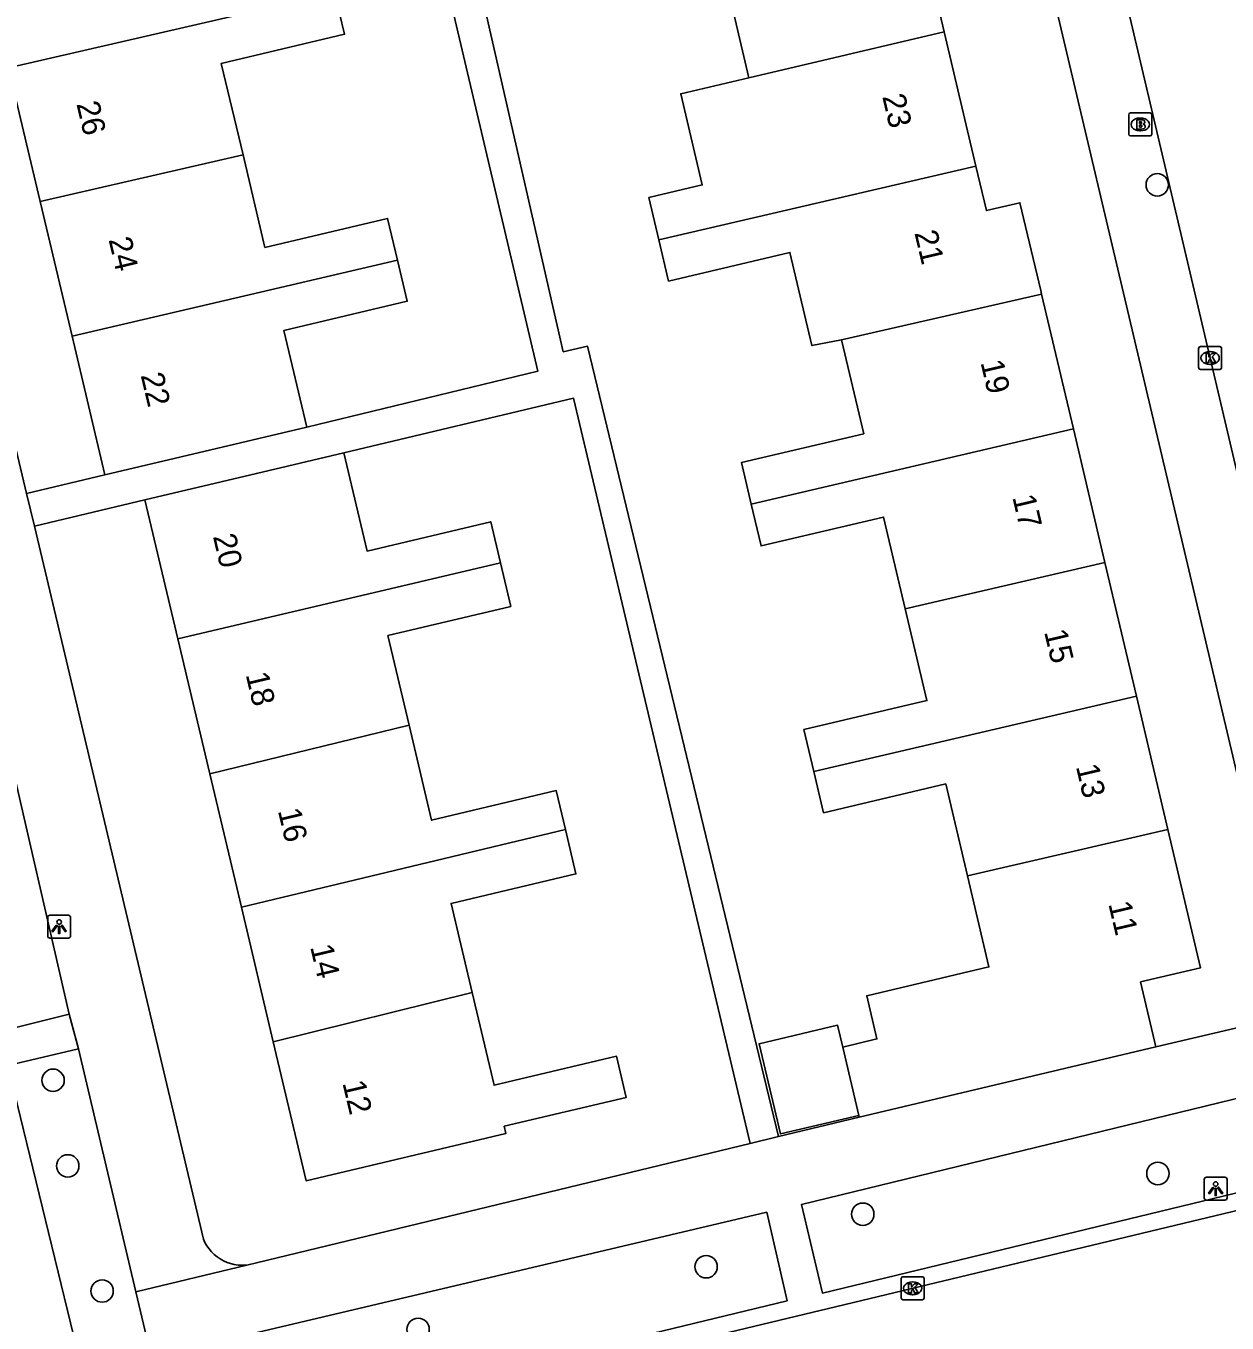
# Model space of a CAD drawing. Extents: x 158038 to 159242, y 380133 to 381214.
# Drawn here: x 158544.2 to 158596.6, y 380781.7 to 380838.3 of the extents above; entities that cross this region are included whole.
import ezdxf

# ---------------------------------------------------------------- set-up
doc = ezdxf.new("R2010")
doc.units = 0
for name, color, linetype in [('IMGEO_Boom', 7, 'Continuous'), ('IMGEO_Brandkraan', 7, 'Continuous'), ('IMGEO_Kolk', 7, 'Continuous'), ('IMGEO_Lichtpunt', 7, 'Continuous'), ('IMGEO_Pand', 7, 'Continuous'), ('IMGEO_Pand_nummerreeks', 7, 'Continuous'), ('IMGEO_Parkeervlak_open', 7, 'Continuous'), ('IMGEO_Rijbaan_lokaal_open', 7, 'Continuous'), ('IMGEO_Voetpad_open', 7, 'Continuous')]:
    doc.layers.add(name, color=color, linetype=linetype)

msp = doc.modelspace()

# ---------------------------------------------------------------- linework, layer by layer
at = {"layer": 'IMGEO_Boom'}
for centre in [(158593.559, 380831.355), (158545.379, 380792.292), (158546.022, 380788.557), (158593.586, 380788.227), (158580.71, 380786.449), (158573.873, 380784.16), (158547.52, 380783.101), (158561.307, 380781.427)]:
    msp.add_circle(centre, 0.489, dxfattribs=at)
at = {"layer": 'IMGEO_Brandkraan'}
for p, q in [((158592.316, 380833.564), (158592.316, 380834.416)), ((158592.391, 380834.49), (158593.243, 380834.49)), ((158592.804, 380834.27), (158592.829, 380834.27)), ((158593.317, 380834.416), (158593.317, 380833.564)), ((158592.827, 380833.71), (158592.802, 380833.71)), ((158593.243, 380833.49), (158592.391, 380833.49))]:
    msp.add_line(p, q, dxfattribs=at)
for points in [[(158592.316, 380833.564), (158592.316, 380834.416)], [(158592.391, 380834.49), (158593.243, 380834.49)], [(158592.664, 380834.19), (158592.664, 380833.79), (158592.877, 380833.79)], [(158592.895, 380834.19), (158592.664, 380834.19)], [(158592.843, 380834.109), (158592.789, 380834.109), (158592.789, 380834.033)], [(158593.317, 380834.416), (158593.317, 380833.564)], [(158592.789, 380834.033), (158592.842, 380834.033)], [(158592.851, 380833.957), (158592.789, 380833.957), (158592.789, 380833.876)], [(158592.789, 380833.876), (158592.851, 380833.876)], [(158593.243, 380833.49), (158592.391, 380833.49)]]:
    msp.add_lwpolyline(points, dxfattribs=at)
for centre, radius, start, end in [((158592.393, 380834.414), 0.0765, 91.552, 178.448), ((158592.393, 380834.414), 0.0765, 91.552, 178.448), ((158592.844, 380834.071), 0.0379, 267.8285, 90.9355), ((158592.899, 380834.045), 0.145, 59.4692, 91.5367), ((158592.924, 380834.092), 0.0922, 285.5137, 58.1501), ((158593.241, 380834.414), 0.0765, 1.552, 88.448), ((158593.241, 380834.414), 0.0765, 1.552, 88.448), ((158592.393, 380833.566), 0.0765, 181.552, 268.448), ((158592.393, 380833.566), 0.0765, 181.552, 268.448), ((158592.852, 380833.916), 0.0404, 269.8759, 90.5077), ((158592.883, 380834.041), 0.251, 268.6676, 293.5347), ((158592.929, 380833.9), 0.105, 301.3115, 78.989), ((158593.241, 380833.566), 0.0765, 271.552, 358.448), ((158593.241, 380833.566), 0.0765, 271.552, 358.448)]:
    msp.add_arc(centre, radius, start, end, dxfattribs=at)
for centre, major_axis, ratio, start_param, end_param in [((158592.803, 380833.99), (-0.387, 0.002), 0.722429, 4.712389, 7.853982), ((158592.828, 380833.99), (-0.39, 0.002), 0.717154, 1.570796, 4.712389)]:
    msp.add_ellipse(centre, major_axis=major_axis, ratio=ratio, start_param=start_param, end_param=end_param, dxfattribs=at)
at = {"layer": 'IMGEO_Kolk'}
for p, q in [((158595.365, 380823.377), (158595.365, 380824.229)), ((158595.44, 380824.303), (158596.292, 380824.303)), ((158595.853, 380824.083), (158595.878, 380824.083)), ((158596.366, 380824.229), (158596.366, 380823.377)), ((158595.876, 380823.523), (158595.851, 380823.523)), ((158596.292, 380823.303), (158595.44, 380823.303)), ((158582.386, 380782.795), (158582.386, 380783.647)), ((158582.461, 380783.721), (158583.313, 380783.721)), ((158582.874, 380783.501), (158582.899, 380783.501)), ((158583.387, 380783.647), (158583.387, 380782.795)), ((158583.313, 380782.721), (158582.461, 380782.721)), ((158582.897, 380782.941), (158582.872, 380782.941))]:
    msp.add_line(p, q, dxfattribs=at)
for points in [[(158595.365, 380823.377), (158595.365, 380824.229)], [(158595.44, 380824.303), (158596.292, 380824.303)], [(158595.686, 380824.003), (158595.809, 380824.003), (158595.809, 380823.852), (158595.939, 380824.003), (158596.103, 380824.003), (158595.957, 380823.852), (158596.11, 380823.603), (158595.958, 380823.603), (158595.873, 380823.767), (158595.809, 380823.7), (158595.809, 380823.603), (158595.686, 380823.603), (158595.686, 380824.003)], [(158596.366, 380824.229), (158596.366, 380823.377)], [(158596.292, 380823.303), (158595.44, 380823.303)], [(158582.386, 380782.795), (158582.386, 380783.647)], [(158582.461, 380783.721), (158583.313, 380783.721)], [(158582.707, 380783.421), (158582.83, 380783.421), (158582.83, 380783.27), (158582.96, 380783.421), (158583.124, 380783.421), (158582.978, 380783.27), (158583.131, 380783.021), (158582.979, 380783.021), (158582.894, 380783.185), (158582.83, 380783.118), (158582.83, 380783.021), (158582.707, 380783.021), (158582.707, 380783.421)], [(158583.387, 380783.647), (158583.387, 380782.795)], [(158583.313, 380782.721), (158582.461, 380782.721)]]:
    msp.add_lwpolyline(points, dxfattribs=at)
for centre, start, end in [((158595.442, 380824.227), 91.552, 178.448), ((158595.442, 380824.227), 91.552, 178.448), ((158596.29, 380824.227), 1.552, 88.448), ((158596.29, 380824.227), 1.552, 88.448), ((158595.442, 380823.379), 181.552, 268.448), ((158595.442, 380823.379), 181.552, 268.448), ((158596.29, 380823.379), 271.552, 358.448), ((158596.29, 380823.379), 271.552, 358.448), ((158582.463, 380783.645), 91.552, 178.448), ((158582.463, 380783.645), 91.552, 178.448), ((158583.311, 380783.645), 1.552, 88.448), ((158583.311, 380783.645), 1.552, 88.448), ((158582.463, 380782.797), 181.552, 268.448), ((158582.463, 380782.797), 181.552, 268.448), ((158583.311, 380782.797), 271.552, 358.448), ((158583.311, 380782.797), 271.552, 358.448)]:
    msp.add_arc(centre, 0.0765, start, end, dxfattribs=at)
for centre, major_axis, ratio, start_param, end_param in [((158595.852, 380823.803), (-0.387, 0.002), 0.722429, 4.712389, 7.853982), ((158595.877, 380823.803), (-0.39, 0.002), 0.717154, 1.570796, 4.712389), ((158582.873, 380783.221), (-0.387, 0.002), 0.722429, 4.712389, 7.853982), ((158582.898, 380783.221), (-0.39, 0.002), 0.717154, 1.570796, 4.712389)]:
    msp.add_ellipse(centre, major_axis=major_axis, ratio=ratio, start_param=start_param, end_param=end_param, dxfattribs=at)
at = {"layer": 'IMGEO_Lichtpunt'}
for p, q in [((158545.147, 380799.399), (158545.147, 380798.592)), ((158545.147, 380799.399), (158545.147, 380798.592)), ((158546.049, 380799.494), (158545.241, 380799.494)), ((158546.049, 380799.494), (158545.241, 380799.494)), ((158546.143, 380798.592), (158546.143, 380799.399)), ((158546.143, 380798.592), (158546.143, 380799.399)), ((158545.241, 380798.498), (158546.049, 380798.498)), ((158545.241, 380798.498), (158546.049, 380798.498)), ((158595.608, 380787.97), (158595.608, 380787.163)), ((158595.608, 380787.97), (158595.608, 380787.163)), ((158596.51, 380788.065), (158595.702, 380788.065)), ((158596.51, 380788.065), (158595.702, 380788.065)), ((158596.604, 380787.163), (158596.604, 380787.97)), ((158596.604, 380787.163), (158596.604, 380787.97)), ((158595.702, 380787.069), (158596.51, 380787.069)), ((158595.702, 380787.069), (158596.51, 380787.069))]:
    msp.add_line(p, q, dxfattribs=at)
for points in [[(158545.521, 380799.063), (158545.56, 380799.035), (158545.372, 380798.773), (158545.334, 380798.8), (158545.521, 380799.063)], [(158545.623, 380799.015), (158545.67, 380799.015), (158545.67, 380798.693), (158545.623, 380798.693), (158545.623, 380799.015)], [(158545.733, 380799.035), (158545.771, 380799.062), (158545.958, 380798.8), (158545.919, 380798.772), (158545.733, 380799.035)], [(158595.982, 380787.634), (158596.021, 380787.606), (158595.833, 380787.344), (158595.795, 380787.371), (158595.982, 380787.634)], [(158596.084, 380787.586), (158596.131, 380787.586), (158596.131, 380787.264), (158596.084, 380787.264), (158596.084, 380787.586)], [(158596.194, 380787.606), (158596.232, 380787.633), (158596.419, 380787.371), (158596.38, 380787.343), (158596.194, 380787.606)]]:
    msp.add_lwpolyline(points, dxfattribs=at)
for centre in [(158545.646, 380799.197), (158596.107, 380787.768)]:
    msp.add_circle(centre, 0.0994, dxfattribs=at)
for centre, start, end in [((158545.241, 380799.399), 90, 180), ((158545.241, 380799.399), 90, 180), ((158546.049, 380799.399), 0, 90), ((158546.049, 380799.399), 0, 90), ((158545.241, 380798.592), 180, 270), ((158545.241, 380798.592), 180, 270), ((158546.049, 380798.592), 270, 0), ((158546.049, 380798.592), 270, 360), ((158595.702, 380787.97), 90, 180), ((158595.702, 380787.97), 90, 180), ((158596.51, 380787.97), 0, 90), ((158596.51, 380787.97), 0, 90), ((158595.702, 380787.163), 180, 270), ((158595.702, 380787.163), 180, 270), ((158596.51, 380787.163), 270, 0), ((158596.51, 380787.163), 270, 360)]:
    msp.add_arc(centre, 0.0946, start, end, dxfattribs=at)
at = {"layer": 'IMGEO_Pand'}
for points in [[(158582.878, 380843.886), (158584.261, 380838.026)], [(158575.745, 380836.029), (158574.791, 380840.071), (158569.436, 380838.807), (158569.011, 380840.606)], [(158543.432, 380836.465), (158557.666, 380839.75)], [(158557.666, 380839.75), (158558.098, 380837.927), (158552.721, 380836.653), (158553.668, 380832.657)], [(158584.261, 380838.026), (158575.745, 380836.029)], [(158584.261, 380838.026), (158585.642, 380832.176)], [(158544.817, 380830.623), (158543.432, 380836.465)], [(158571.812, 380828.951), (158571.376, 380830.801), (158573.703, 380831.35), (158572.769, 380835.331), (158575.745, 380836.029)], [(158544.817, 380830.623), (158553.668, 380832.657)], [(158553.668, 380832.657), (158554.623, 380828.624), (158559.975, 380829.892), (158560.408, 380828.066)], [(158585.642, 380832.176), (158571.812, 380828.951)], [(158588.511, 380826.586), (158588.472, 380826.752), (158587.569, 380830.577), (158586.101, 380830.23), (158585.642, 380832.176)], [(158546.208, 380824.752), (158544.817, 380830.623)], [(158571.812, 380828.951), (158572.235, 380827.16), (158577.531, 380828.41), (158578.491, 380824.343), (158579.782, 380824.594)], [(158560.408, 380828.066), (158546.208, 380824.752)], [(158560.408, 380828.066), (158560.832, 380826.277), (158555.448, 380825.001), (158556.446, 380820.79)], [(158579.782, 380824.594), (158588.511, 380826.586)], [(158588.511, 380826.586), (158589.898, 380820.711)], [(158547.641, 380818.703), (158546.208, 380824.752)], [(158575.845, 380817.432), (158575.418, 380819.24), (158580.749, 380820.498), (158579.782, 380824.594)], [(158556.446, 380820.79), (158552.507, 380819.856), (158547.641, 380818.703)], [(158589.898, 380820.711), (158575.845, 380817.432)], [(158589.898, 380820.711), (158591.275, 380814.876)], [(158549.386, 380817.61), (158554.252, 380818.763), (158558.068, 380819.667)], [(158564.901, 380814.871), (158564.478, 380816.657), (158559.084, 380815.379), (158558.068, 380819.667)], [(158549.386, 380817.61), (158550.821, 380811.553)], [(158582.562, 380812.855), (158581.616, 380816.865), (158576.276, 380815.604), (158575.845, 380817.432)], [(158564.901, 380814.871), (158550.821, 380811.553)], [(158560.916, 380807.781), (158559.988, 380811.695), (158565.352, 380812.967), (158564.901, 380814.871)], [(158591.275, 380814.876), (158582.562, 380812.855)], [(158591.275, 380814.876), (158592.651, 380809.05)], [(158578.579, 380805.759), (158578.145, 380807.595), (158583.505, 380808.86), (158582.562, 380812.855)], [(158550.821, 380811.553), (158552.217, 380805.662)], [(158578.579, 380805.759), (158592.651, 380809.05)], [(158592.651, 380809.05), (158594.024, 380803.234)], [(158552.217, 380805.662), (158560.916, 380807.781)], [(158560.916, 380807.781), (158561.897, 380803.64), (158567.332, 380804.928), (158567.735, 380803.227)], [(158553.597, 380799.838), (158552.217, 380805.662)], [(158585.276, 380801.21), (158584.329, 380805.224), (158579.002, 380803.967), (158578.579, 380805.759)], [(158567.735, 380803.227), (158553.597, 380799.838)], [(158563.667, 380796.124), (158562.747, 380800.007), (158568.193, 380801.298), (158567.735, 380803.227)], [(158594.024, 380803.234), (158585.276, 380801.21)], [(158594.024, 380803.234), (158595.447, 380797.204), (158592.829, 380796.586), (158593.5, 380793.746)], [(158585.276, 380801.21), (158586.213, 380797.239), (158580.884, 380795.981), (158581.329, 380794.095), (158579.837, 380793.743)], [(158553.597, 380799.838), (158554.986, 380793.976)], [(158554.986, 380793.976), (158563.667, 380796.124)], [(158554.986, 380793.976), (158556.423, 380787.909), (158565.138, 380789.974), (158565.064, 380790.285), (158570.391, 380791.548), (158569.966, 380793.345), (158564.626, 380792.079), (158563.667, 380796.124)], [(158579.837, 380793.743), (158579.612, 380794.695), (158576.186, 380793.887), (158577.115, 380789.953), (158580.541, 380790.762)], [(158580.541, 380790.762), (158579.837, 380793.743)], [(158580.558, 380790.689), (158593.5, 380793.746)], [(158580.541, 380790.762), (158580.558, 380790.689)]]:
    msp.add_lwpolyline(points, dxfattribs=at)
at = {"layer": 'IMGEO_Parkeervlak_open'}
msp.add_lwpolyline([(158543.412, 380792.934), (158546.695, 380779.447), (158541.806, 380778.346)], dxfattribs=at)
at = {"layer": 'IMGEO_Rijbaan_lokaal_open'}
for points in [[(158585.362, 380867.367), (158585.66, 380866.767), (158585.904, 380866.143), (158600.289, 380805.01), (158601.755, 380798.591), (158602.585, 380794.954), (158604.015, 380788.692), (158605.732, 380781.448), (158613.185, 380750), (158615.123, 380741.822), (158616.028, 380738.005), (158618.646, 380727.333), (158618.975, 380725.857)], [(158601.167, 380787.602), (158550.781, 380775.523)]]:
    msp.add_lwpolyline(points, dxfattribs=at)
at = {"layer": 'IMGEO_Voetpad_open'}
for points in [[(158599.515, 380795.166), (158582.927, 380865.443), (158582.859, 380865.59), (158582.778, 380865.73), (158582.685, 380865.862), (158582.58, 380865.985), (158582.465, 380866.099), (158582.34, 380866.201), (158582.206, 380866.292), (158582.065, 380866.371), (158581.918, 380866.437), (158581.765, 380866.49), (158581.608, 380866.528), (158581.448, 380866.553), (158581.286, 380866.563), (158581.125, 380866.558), (158580.964, 380866.54)], [(158535.255, 380855.756), (158544.228, 380817.894)], [(158561.065, 380852.917), (158567.641, 380824.075), (158568.7, 380824.316), (158577.028, 380789.836)], [(158559.622, 380852.545), (158566.537, 380823.228), (158556.446, 380820.79)], [(158558.068, 380819.667), (158568.094, 380822.042), (158575.794, 380789.538)], [(158547.641, 380818.703), (158544.228, 380817.894)], [(158544.228, 380817.894), (158544.566, 380816.468)], [(158544.566, 380816.468), (158549.386, 380817.61)], [(158553.836, 380784.234), (158553.78, 380784.229), (158553.615, 380784.224), (158553.45, 380784.234), (158553.287, 380784.259), (158553.127, 380784.298), (158552.971, 380784.351), (158552.82, 380784.418), (158552.675, 380784.498), (158552.539, 380784.591), (158552.411, 380784.695), (158552.293, 380784.811), (158552.186, 380784.936), (158552.091, 380785.071), (158552.008, 380785.214), (158551.938, 380785.363), (158544.566, 380816.468)], [(158543.309, 380807.269), (158546.085, 380795.171)], [(158546.085, 380795.171), (158538.226, 380793.212)], [(158546.49, 380793.669), (158546.085, 380795.171)], [(158593.5, 380793.746), (158599.515, 380795.166)], [(158543.412, 380792.934), (158546.49, 380793.669)], [(158548.998, 380783.065), (158546.49, 380793.669)], [(158601.053, 380788.365), (158578.947, 380783.008), (158578.035, 380786.868), (158600.252, 380792.284)], [(158577.028, 380789.836), (158580.558, 380790.689)], [(158575.794, 380789.538), (158553.836, 380784.234)], [(158575.794, 380789.538), (158577.028, 380789.836)], [(158576.522, 380786.533), (158577.413, 380782.673), (158553.963, 380777.002), (158552.994, 380780.981), (158576.522, 380786.533)], [(158553.836, 380784.234), (158548.998, 380783.065)], [(158548.998, 380783.065), (158550.781, 380775.523)]]:
    msp.add_lwpolyline(points, dxfattribs=at)

# ---------------------------------------------------------------- texts
at = {"layer": 'IMGEO_Pand_nummerreeks'}
for s, rotation, p in [('23', 283.2796, (158581.555, 380835.21)), ('26', 283.3305, (158546.395, 380834.888)), ('24', 283.3305, (158547.798, 380828.968)), ('21', 283.281, (158582.96, 380829.263)), ('19', 283.2819, (158585.843, 380823.61)), ('22', 283.3305, (158549.2, 380823.051)), ('17', 283.2819, (158587.231, 380817.734)), ('20', 283.3292, (158552.352, 380816.021)), ('15', 283.2819, (158588.618, 380811.858)), ('18', 283.3292, (158553.78, 380809.992)), ('13', 283.2819, (158590.005, 380805.981)), ('16', 283.3292, (158555.186, 380804.055)), ('11', 283.281, (158591.419, 380799.993)), ('14', 283.3292, (158556.594, 380798.115)), ('12', 283.3292, (158558.001, 380792.178))]:
    msp.add_text(s, height=1, rotation=rotation, dxfattribs=at).set_placement(p)

doc.saveas('drawing.dxf')
